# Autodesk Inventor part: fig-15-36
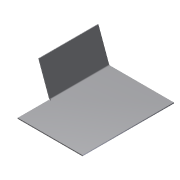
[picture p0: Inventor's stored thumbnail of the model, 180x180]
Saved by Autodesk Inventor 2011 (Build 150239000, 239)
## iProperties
Created: 2005-03
Part Number: fig-15-36
Document SubType Name: Sheet Metal
Designer: CADCIM
Manufacturer: Standard
Standards Organization: Custom
Density: 1 g/cm^3
Sheet Metal Rule: Default
Author: CADCIM
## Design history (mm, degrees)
node "Face1"
  sketch "Sketch1"
    geometry: L1 (31.393, 35.714)-(-17.775, 35.714); L2 (-17.775, 35.714)-(-17.775, 5.625); L3 (-17.775, 5.625)-(-1.5, 5.625); L4 (-1.5, 5.625)-(-1.5, -10.705); L5 (-1.5, -10.705)-(31.393, -10.705); L6 (31.393, -10.705)-(31.393, 35.714)
    constraints: 12 end point, 4 parallel, 1 horizontal, 1 perpendicular
sketch "Sketch3"
  geometry: L1 (16.275, -30.089)-(16.275, 0); L2 (16.275, -46.42)-(16.275, -30.089) reference; L3 (16.275, -30.089)-(0, -30.089) reference; L4 (0, 0)-(49.168, 0) reference
  constraints: 3 point on line, 2 end point, 1 vertical
feature "Fold1" sketch "Sketch3" dims "d1" = 0.5 (= BendReliefWidth), "d2" = 0.25 (= BendReliefDepth), "d3" = 1 (= MinimumRemnant), "d4" = 0.5 (= BendRadius), "d5" = 70 deg, "d6" = 0.5 (= BendRadius), "SeamGap" = 0.01, "Thickness" = 0.5
body "Solid1"
face "Plate1" dims "Thickness" = 0.5
other parameters: "BendRadius" = 0.5 (= Thickness), "BendReliefWidth" = 0.5 (= Thickness), "BendReliefDepth" = 0.25 (= 0.5 x Thickness), "CornerReliefSize" = 2 (= 4 x Thickness), "MinimumRemnant" = 1 (= 2 x Thickness), "TransitionRadius" = 0.5 (= BendRadius), "d0" = 0.5 (= BendRadius), "JacobiRadiusSize" = 0.5 (= Thickness), "GapSize" = 0.5 (= Thickness)
